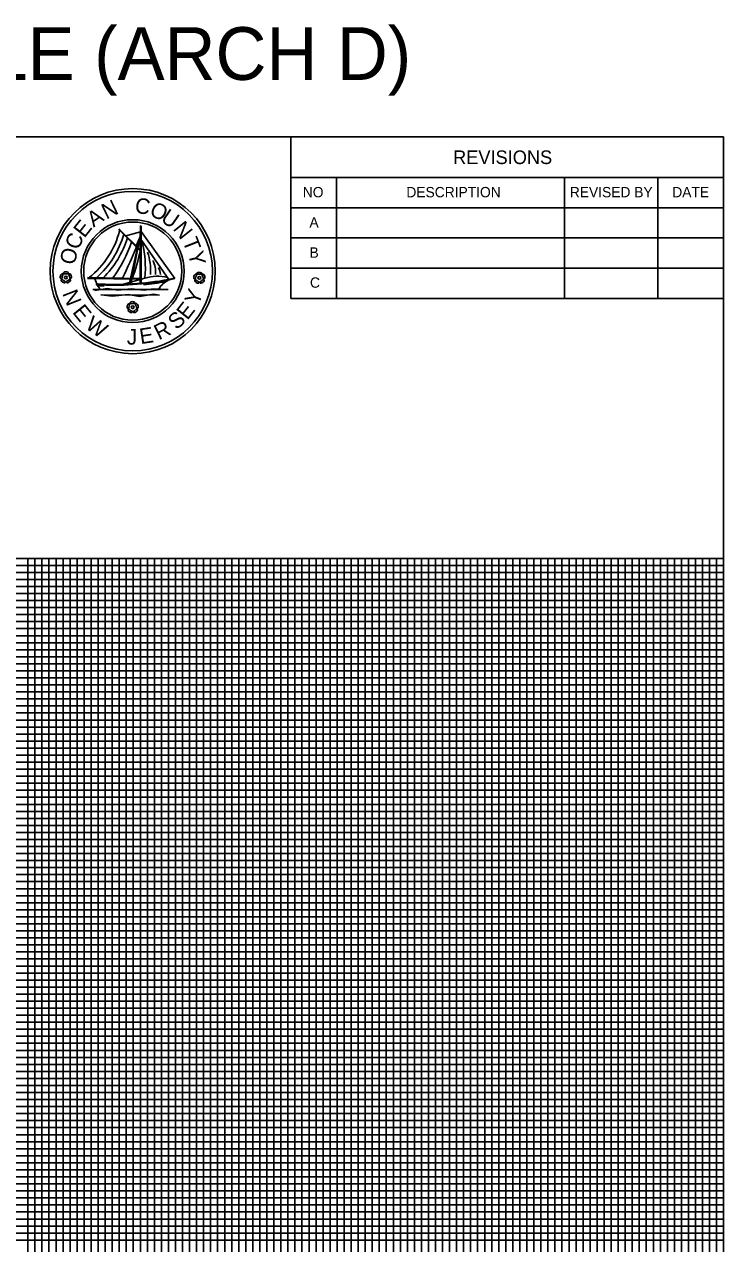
# Model space of a CAD drawing. Extents: x -6359 to 1641, y 3001 to 24737.
# Drawn here: x -2339 to 1641, y 17798 to 24737 of the extents above; entities that cross this region are included whole.
import ezdxf

# ---------------------------------------------------------------- set-up
doc = ezdxf.new("R2010")
doc.units = 0
for name, color, linetype in [('_grid', 7, 'Continuous'), ('Border', 7, 'Continuous'), ('Level 1', 7, 'Continuous'), ('TB - ON', 7, 'Continuous'), ('Title Block', 7, 'Continuous')]:
    doc.layers.add(name, color=color, linetype=linetype)

msp = doc.modelspace()

# ---------------------------------------------------------------- linework, layer by layer
at = {"layer": '_grid'}
for p, q in [((1641.3, 21698.2), (-6358.7, 21698.2)), ((1641.3, 21698.2), (-6358.7, 21698.2)), ((1641.3, 21658.2), (-6358.7, 21658.2)), ((-2318.7, 12898.2), (-2318.7, 21698.2)), ((-2278.7, 12898.2), (-2278.7, 21698.2)), ((-2238.7, 12898.2), (-2238.7, 21698.2)), ((-2198.7, 12898.2), (-2198.7, 21698.2)), ((-2158.7, 12898.2), (-2158.7, 21698.2)), ((-2118.7, 12898.2), (-2118.7, 21698.2)), ((-2078.7, 12898.2), (-2078.7, 21698.2)), ((-2038.7, 12898.2), (-2038.7, 21698.2)), ((-1998.7, 12898.2), (-1998.7, 21698.2)), ((-1958.7, 21698.2), (-1958.7, 12898.2)), ((-1958.7, 12898.2), (-1958.7, 21698.2)), ((-1918.7, 12898.2), (-1918.7, 21698.2)), ((-1878.7, 12898.2), (-1878.7, 21698.2)), ((-1838.7, 12898.2), (-1838.7, 21698.2)), ((-1798.7, 12898.2), (-1798.7, 21698.2)), ((-1758.7, 12898.2), (-1758.7, 21698.2)), ((-1718.7, 12898.2), (-1718.7, 21698.2)), ((-1678.7, 12898.2), (-1678.7, 21698.2)), ((-1638.7, 12898.2), (-1638.7, 21698.2)), ((-1598.7, 12898.2), (-1598.7, 21698.2)), ((-1558.7, 21698.2), (-1558.7, 12898.2)), ((-1558.7, 12898.2), (-1558.7, 21698.2)), ((-1518.7, 12898.2), (-1518.7, 21698.2)), ((-1478.7, 12898.2), (-1478.7, 21698.2)), ((-1438.7, 12898.2), (-1438.7, 21698.2)), ((-1398.7, 12898.2), (-1398.7, 21698.2)), ((-1358.7, 12898.2), (-1358.7, 21698.2)), ((-1318.7, 12898.2), (-1318.7, 21698.2)), ((-1278.7, 12898.2), (-1278.7, 21698.2)), ((-1238.7, 12898.2), (-1238.7, 21698.2)), ((-1198.7, 12898.2), (-1198.7, 21698.2)), ((-1158.7, 21698.2), (-1158.7, 12898.2)), ((-1158.7, 12898.2), (-1158.7, 21698.2)), ((-1118.7, 12898.2), (-1118.7, 21698.2)), ((-1078.7, 12898.2), (-1078.7, 21698.2)), ((-1038.7, 12898.2), (-1038.7, 21698.2)), ((-998.7, 12898.2), (-998.7, 21698.2)), ((-958.7, 12898.2), (-958.7, 21698.2)), ((-918.7, 12898.2), (-918.7, 21698.2)), ((-878.7, 12898.2), (-878.7, 21698.2)), ((-838.7, 12898.2), (-838.7, 21698.2)), ((-798.7, 12898.2), (-798.7, 21698.2)), ((-758.7, 21698.2), (-758.7, 12898.2)), ((-758.7, 12898.2), (-758.7, 21698.2)), ((-718.7, 12898.2), (-718.7, 21698.2)), ((-678.7, 12898.2), (-678.7, 21698.2)), ((-638.7, 12898.2), (-638.7, 21698.2)), ((-598.7, 12898.2), (-598.7, 21698.2)), ((-558.7, 12898.2), (-558.7, 21698.2)), ((-518.7, 12898.2), (-518.7, 21698.2)), ((-478.7, 12898.2), (-478.7, 21698.2)), ((-438.7, 12898.2), (-438.7, 21698.2)), ((-398.7, 12898.2), (-398.7, 21698.2)), ((-358.7, 21698.2), (-358.7, 12898.2)), ((-358.7, 12898.2), (-358.7, 21698.2)), ((-318.7, 12898.2), (-318.7, 21698.2)), ((-278.7, 12898.2), (-278.7, 21698.2)), ((-238.7, 12898.2), (-238.7, 21698.2)), ((-198.7, 12898.2), (-198.7, 21698.2)), ((-158.7, 12898.2), (-158.7, 21698.2)), ((-118.7, 12898.2), (-118.7, 21698.2)), ((-78.7, 12898.2), (-78.7, 21698.2)), ((-38.7, 12898.2), (-38.7, 21698.2)), ((1.3, 12898.2), (1.3, 21698.2)), ((41.3, 21698.2), (41.3, 12898.2)), ((41.3, 12898.2), (41.3, 21698.2)), ((81.3, 12898.2), (81.3, 21698.2)), ((121.3, 12898.2), (121.3, 21698.2)), ((161.3, 12898.2), (161.3, 21698.2)), ((201.3, 12898.2), (201.3, 21698.2)), ((241.3, 12898.2), (241.3, 21698.2)), ((281.3, 12898.2), (281.3, 21698.2)), ((321.3, 12898.2), (321.3, 21698.2)), ((361.3, 12898.2), (361.3, 21698.2)), ((401.3, 12898.2), (401.3, 21698.2)), ((441.3, 21698.2), (441.3, 12898.2)), ((441.3, 12898.2), (441.3, 21698.2)), ((481.3, 12898.2), (481.3, 21698.2)), ((521.3, 12898.2), (521.3, 21698.2)), ((561.3, 12898.2), (561.3, 21698.2)), ((601.3, 12898.2), (601.3, 21698.2)), ((641.3, 12898.2), (641.3, 21698.2)), ((681.3, 12898.2), (681.3, 21698.2)), ((721.3, 12898.2), (721.3, 21698.2)), ((761.3, 12898.2), (761.3, 21698.2)), ((801.3, 12898.2), (801.3, 21698.2)), ((841.3, 21698.2), (841.3, 12898.2)), ((841.3, 12898.2), (841.3, 21698.2)), ((881.3, 12898.2), (881.3, 21698.2)), ((921.3, 12898.2), (921.3, 21698.2)), ((961.3, 12898.2), (961.3, 21698.2)), ((1001.3, 12898.2), (1001.3, 21698.2)), ((1041.3, 12898.2), (1041.3, 21698.2)), ((1081.3, 12898.2), (1081.3, 21698.2)), ((1121.3, 12898.2), (1121.3, 21698.2)), ((1161.3, 12898.2), (1161.3, 21698.2)), ((1201.3, 12898.2), (1201.3, 21698.2)), ((1241.3, 21698.2), (1241.3, 12898.2)), ((1241.3, 12898.2), (1241.3, 21698.2)), ((1281.3, 12898.2), (1281.3, 21698.2)), ((1321.3, 12898.2), (1321.3, 21698.2)), ((1361.3, 12898.2), (1361.3, 21698.2)), ((1401.3, 12898.2), (1401.3, 21698.2)), ((1441.3, 12898.2), (1441.3, 21698.2)), ((1481.3, 12898.2), (1481.3, 21698.2)), ((1521.3, 12898.2), (1521.3, 21698.2)), ((1561.3, 12898.2), (1561.3, 21698.2)), ((1601.3, 12898.2), (1601.3, 21698.2)), ((1641.3, 12898.2), (1641.3, 21698.2)), ((1641.3, 21698.2), (1641.3, 12898.2)), ((1641.3, 21618.2), (-6358.7, 21618.2)), ((1641.3, 21578.2), (-6358.7, 21578.2)), ((1641.3, 21538.2), (-6358.7, 21538.2)), ((1641.3, 21498.2), (-6358.7, 21498.2)), ((1641.3, 21458.2), (-6358.7, 21458.2)), ((1641.3, 21418.2), (-6358.7, 21418.2)), ((1641.3, 21378.2), (-6358.7, 21378.2)), ((1641.3, 21338.2), (-6358.7, 21338.2)), ((1641.3, 21298.2), (-6358.7, 21298.2)), ((1641.3, 21298.2), (-6358.7, 21298.2)), ((1641.3, 21258.2), (-6358.7, 21258.2)), ((1641.3, 21218.2), (-6358.7, 21218.2)), ((1641.3, 21178.2), (-6358.7, 21178.2)), ((1641.3, 21138.2), (-6358.7, 21138.2)), ((1641.3, 21098.2), (-6358.7, 21098.2)), ((1641.3, 21058.2), (-6358.7, 21058.2)), ((1641.3, 21018.2), (-6358.7, 21018.2)), ((1641.3, 20978.2), (-6358.7, 20978.2)), ((1641.3, 20938.2), (-6358.7, 20938.2)), ((1641.3, 20898.2), (-6358.7, 20898.2)), ((1641.3, 20898.2), (-6358.7, 20898.2)), ((1641.3, 20858.2), (-6358.7, 20858.2)), ((1641.3, 20818.2), (-6358.7, 20818.2)), ((1641.3, 20778.2), (-6358.7, 20778.2)), ((1641.3, 20738.2), (-6358.7, 20738.2)), ((1641.3, 20698.2), (-6358.7, 20698.2)), ((1641.3, 20658.2), (-6358.7, 20658.2)), ((1641.3, 20618.2), (-6358.7, 20618.2)), ((1641.3, 20578.2), (-6358.7, 20578.2)), ((1641.3, 20538.2), (-6358.7, 20538.2)), ((1641.3, 20498.2), (-6358.7, 20498.2)), ((1641.3, 20498.2), (-6358.7, 20498.2)), ((1641.3, 20458.2), (-6358.7, 20458.2)), ((1641.3, 20418.2), (-6358.7, 20418.2)), ((1641.3, 20378.2), (-6358.7, 20378.2)), ((1641.3, 20338.2), (-6358.7, 20338.2)), ((1641.3, 20298.2), (-6358.7, 20298.2)), ((1641.3, 20258.2), (-6358.7, 20258.2)), ((1641.3, 20218.2), (-6358.7, 20218.2)), ((1641.3, 20178.2), (-6358.7, 20178.2)), ((1641.3, 20138.2), (-6358.7, 20138.2)), ((1641.3, 20098.2), (-6358.7, 20098.2)), ((1641.3, 20098.2), (-6358.7, 20098.2)), ((1641.3, 20058.2), (-6358.7, 20058.2)), ((1641.3, 20018.2), (-6358.7, 20018.2)), ((1641.3, 19978.2), (-6358.7, 19978.2)), ((1641.3, 19938.2), (-6358.7, 19938.2)), ((1641.3, 19898.2), (-6358.7, 19898.2)), ((1641.3, 19858.2), (-6358.7, 19858.2)), ((1641.3, 19818.2), (-6358.7, 19818.2)), ((1641.3, 19778.2), (-6358.7, 19778.2)), ((1641.3, 19738.2), (-6358.7, 19738.2)), ((1641.3, 19698.2), (-6358.7, 19698.2)), ((1641.3, 19698.2), (-6358.7, 19698.2)), ((1641.3, 19658.2), (-6358.7, 19658.2)), ((1641.3, 19618.2), (-6358.7, 19618.2)), ((1641.3, 19578.2), (-6358.7, 19578.2)), ((1641.3, 19538.2), (-6358.7, 19538.2)), ((1641.3, 19498.2), (-6358.7, 19498.2)), ((1641.3, 19458.2), (-6358.7, 19458.2)), ((1641.3, 19418.2), (-6358.7, 19418.2)), ((1641.3, 19378.2), (-6358.7, 19378.2)), ((1641.3, 19338.2), (-6358.7, 19338.2)), ((1641.3, 19298.2), (-6358.7, 19298.2)), ((1641.3, 19298.2), (-6358.7, 19298.2)), ((1641.3, 19258.2), (-6358.7, 19258.2)), ((1641.3, 19218.2), (-6358.7, 19218.2)), ((1641.3, 19178.2), (-6358.7, 19178.2)), ((1641.3, 19138.2), (-6358.7, 19138.2)), ((1641.3, 19098.2), (-6358.7, 19098.2)), ((1641.3, 19058.2), (-6358.7, 19058.2)), ((1641.3, 19018.2), (-6358.7, 19018.2)), ((1641.3, 18978.2), (-6358.7, 18978.2)), ((1641.3, 18938.2), (-6358.7, 18938.2)), ((1641.3, 18898.2), (-6358.7, 18898.2)), ((1641.3, 18898.2), (-6358.7, 18898.2)), ((1641.3, 18858.2), (-6358.7, 18858.2)), ((1641.3, 18818.2), (-6358.7, 18818.2)), ((1641.3, 18778.2), (-6358.7, 18778.2)), ((1641.3, 18738.2), (-6358.7, 18738.2)), ((1641.3, 18698.2), (-6358.7, 18698.2)), ((1641.3, 18658.2), (-6358.7, 18658.2)), ((1641.3, 18618.2), (-6358.7, 18618.2)), ((1641.3, 18578.2), (-6358.7, 18578.2)), ((1641.3, 18538.2), (-6358.7, 18538.2)), ((1641.3, 18498.2), (-6358.7, 18498.2)), ((1641.3, 18498.2), (-6358.7, 18498.2)), ((1641.3, 18458.2), (-6358.7, 18458.2)), ((1641.3, 18418.2), (-6358.7, 18418.2)), ((1641.3, 18378.2), (-6358.7, 18378.2)), ((1641.3, 18338.2), (-6358.7, 18338.2)), ((1641.3, 18298.2), (-6358.7, 18298.2)), ((1641.3, 18258.2), (-6358.7, 18258.2)), ((1641.3, 18218.2), (-6358.7, 18218.2)), ((1641.3, 18178.2), (-6358.7, 18178.2)), ((1641.3, 18138.2), (-6358.7, 18138.2)), ((1641.3, 18098.2), (-6358.7, 18098.2)), ((1641.3, 18098.2), (-6358.7, 18098.2)), ((1641.3, 18058.2), (-6358.7, 18058.2)), ((1641.3, 18018.2), (-6358.7, 18018.2)), ((1641.3, 17978.2), (-6358.7, 17978.2)), ((1641.3, 17938.2), (-6358.7, 17938.2)), ((1641.3, 17898.2), (-6358.7, 17898.2)), ((1641.3, 17858.2), (-6358.7, 17858.2)), ((1641.3, 17818.2), (-6358.7, 17818.2))]:
    msp.add_line(p, q, dxfattribs=at)
at = {"layer": 'Border'}
for p, q in [((-6358.7, 24098.2), (1641.3, 24098.2)), ((1641.3, 24098.2), (1641.3, 21698.2)), ((1641.3, 21698.2), (1641.3, 12898.2))]:
    msp.add_line(p, q, dxfattribs=at)
at = {"layer": 'TB - ON'}
for p, q in [((1641.3, 24098.2), (-6358.7, 24098.2)), ((-6358.7, 24098.2), (1641.3, 24098.2)), ((-822.7, 23177.8), (-822.7, 24098.2)), ((1641.3, 21698.2), (1641.3, 24098.2)), ((1641.3, 23865.6), (-822.7, 23865.6)), ((-562.1, 23177.8), (-562.1, 23865.6)), ((735.5, 23177.8), (735.5, 23865.6)), ((1267.3, 23177.8), (1267.3, 23865.6)), ((1641.3, 23693.7), (-822.7, 23693.7)), ((-1799.6, 23567.8), (-1679.5, 23449.3)), ((-1796.8, 23570.5), (-1679.9, 23455.1)), ((-1678.7, 23556.3), (-1760.5, 23534.6)), ((-1676, 23550.9), (-1742.3, 23259.6)), ((-1676, 23550.9), (-1731.9, 23260.1)), ((-1701.8, 23477.4), (-1678.8, 23527.3)), ((-1679.5, 23510.8), (-1678.2, 23588.6)), ((-1674.2, 23558.8), (-1482.2, 23290.5)), ((-1673.1, 23510.8), (-1674, 23589.4)), ((-1679.5, 23263.8), (-1679.5, 23510.8)), ((-1673.1, 23264.4), (-1673.1, 23510.8)), ((-1672.2, 23509.4), (-1516.5, 23285.7)), ((1641.3, 23521.7), (-822.7, 23521.7)), ((1641.3, 23349.8), (-822.7, 23349.8)), ((-1679.9, 23287), (-1979.3, 23291.6)), ((-1679.8, 23291.4), (-1979.2, 23296)), ((-1937.3, 23289.4), (-1925.9, 23259.9)), ((-1652.7, 23292), (-1773.8, 23258.3)), ((-1520, 23280.6), (-1482.2, 23290.5)), ((-1519.6, 23285.1), (-1481.6, 23292.1)), ((-1948.5, 23227.8), (-1520.8, 23227.8)), ((-1867.3, 23233.6), (-1938.4, 23223.6)), ((-1903.6, 23197.1), (-1569, 23195.5)), ((-1840, 23190.9), (-1900.3, 23197.3)), ((-1806.9, 23224.2), (-1867.3, 23233.6)), ((-1745.7, 23200.5), (-1840, 23190.9)), ((-1730.8, 23232.8), (-1806.9, 23224.2)), ((-1683.5, 23189.5), (-1745.7, 23200.5)), ((-1657, 23224), (-1730.8, 23232.8)), ((-1604.2, 23201.6), (-1683.5, 23189.5)), ((-1604.3, 23233.1), (-1657, 23224)), ((-1520.8, 23227.8), (-1604.3, 23233.1)), ((-1569, 23195.5), (-1604.2, 23201.6)), ((1641.3, 23177.8), (-822.7, 23177.8))]:
    msp.add_line(p, q, dxfattribs=at)
for centre, radius in [((-1721.9, 23333), 469.8), ((-1721.9, 23333), 454), ((-1721.9, 23333), 292.8), ((-1721.9, 23333), 279.3), ((-2102.6, 23296.7), 7.87), ((-1342.7, 23294.5), 7.87), ((-1722.4, 23127.1), 7.87)]:
    msp.add_circle(centre, radius, dxfattribs=at)
for centre, radius, start, end in [((-2271, 23681.3), 488.5, 307.90444, 346.21233), ((-2271, 23681.3), 516.5, 311.62946, 344.37175), ((-1798.3, 23569.3), 1.94, 39.72611, 230.2739), ((-1676.1, 23588.7), 2.15, 19.75004, 182.7703), ((-2271, 23681.3), 542.4, 314.52857, 342.86997), ((-2409.8, 23723.9), 717.1, 323.15333, 341.66107), ((-5038.8, 24847), 3610.5, 334.50551, 337.58996), ((-2226.3, 23350), 576.5, 354.22434, 16.04693), ((-2860.5, 23697.2), 1206.8, 340.38579, 348.14661), ((-1942.2, 23337.8), 321.5, 355.78399, 18.8142), ((-1736.4, 23326.8), 144.9, 355.16039, 27.78371), ((-2108, 23298.3), 26.5, 137.15758, 188.57474), ((-2124.3, 23313.4), 4.19, 83.65018, 137.15758), ((-2124.5, 23311.6), 6, 49.01818, 83.65018), ((-2123.3, 23313), 4.19, 325.35921, 49.01818), ((-2112.7, 23322.2), 4.19, 116.57474, 177.34614), ((-2111.1, 23322.2), 5.8, 177.34614, 223.93293), ((-2112.3, 23321), 4.19, 223.93293, 289.1485), ((-2102.8, 23302.3), 26.5, 65.15758, 116.57474), ((-2102.3, 23292.2), 26.3, 73.35921, 109.1485), ((-2093.5, 23321.4), 4.19, 253.35921, 337.01818), ((-2093.4, 23322.5), 4.19, 11.65018, 65.15758), ((-2095.2, 23322.2), 6, 337.01818, 11.65018), ((-2082.5, 23313.4), 4.19, 151.93293, 217.1485), ((-2081.1, 23312.7), 5.8, 105.34614, 151.93293), ((-2081.5, 23314.2), 4.19, 44.57474, 105.34614), ((-2097.3, 23298.6), 26.5, 353.15758, 44.57474), ((-1653.7, 23310.1), 89.6, 2.62489, 29.2339), ((-1364.4, 23311.3), 4.19, 83.65018, 137.15758), ((-1364.6, 23309.5), 6, 49.01818, 83.65018), ((-1352.8, 23320), 4.19, 116.57474, 177.34614), ((-1351.2, 23320), 5.8, 177.34614, 223.93293), ((-1352.4, 23318.9), 4.19, 223.93293, 289.1485), ((-1342.9, 23300.1), 26.5, 65.15758, 116.57474), ((-1342.4, 23290), 26.3, 73.35921, 109.1485), ((-1333.6, 23319.3), 4.19, 253.35921, 337.01818), ((-1333.5, 23320.3), 4.19, 11.65018, 65.15758), ((-1335.3, 23320), 6, 337.01818, 11.65018), ((-1321.2, 23310.5), 5.8, 105.34614, 151.93293), ((-1321.6, 23312), 4.19, 44.57474, 105.34614), ((-2130, 23295), 4.19, 188.57474, 249.34614), ((-2129.4, 23296.5), 5.8, 249.34614, 295.93293), ((-2125.2, 23281.2), 4.19, 155.65018, 209.15758), ((-2123.6, 23280.5), 6, 121.01818, 155.65018), ((-2105.8, 23292.1), 26.5, 209.15758, 260.57474), ((-2128.7, 23295), 4.19, 295.93293, 1.1485), ((-2124.5, 23282.1), 4.19, 37.35921, 121.01818), ((-2098.2, 23295.7), 26.3, 145.35921, 181.1485), ((-2100.3, 23300.6), 26.3, 217.35921, 253.1485), ((-2109.4, 23270.1), 4.19, 260.57474, 321.34614), ((-2109.1, 23271.4), 4.19, 7.93293, 73.1485), ((-2110.7, 23271.1), 5.8, 321.34614, 7.93293), ((-2095.4, 23271.4), 4.19, 109.35921, 193.01818), ((-2093.7, 23271.8), 6, 193.01818, 227.65018), ((-2094.9, 23270.4), 4.19, 227.65018, 281.15758), ((-2105.6, 23300.2), 26.3, 289.35921, 325.1485), ((-2099.2, 23292.3), 26.5, 281.15758, 332.57474), ((-2106.8, 23295), 26.3, 1.35921, 37.1485), ((-2080.5, 23282.7), 4.19, 79.93293, 145.1485), ((-2076.3, 23295.7), 4.19, 181.35921, 265.01818), ((-2080.8, 23281.1), 5.8, 33.34614, 79.93293), ((-2076.1, 23297.5), 6, 265.01818, 299.65018), ((-2079.5, 23282), 4.19, 332.57474, 33.34614), ((-2075.2, 23295.9), 4.19, 299.65018, 353.15758), ((-1829.9, 25004.1), 1746.8, 266.69795, 280.23111), ((-2005.7, 23182.8), 107.9, 25.67969, 45.85063), ((-1829.9, 25004.1), 1751.2, 266.85432, 280.194), ((-1829.9, 25004.1), 1756.4, 267.01816, 268.24015), ((-1829.9, 25004.1), 1756.4, 275.55716, 279.66812), ((-1580.7, 23083.5), 220.6, 75.17554, 109.03876), ((-1476.5, 23181.1), 108.6, 113.60998, 152.69479), ((-1348.1, 23296.1), 26.5, 137.15758, 188.57474), ((-1370.1, 23292.8), 4.19, 188.57474, 249.34614), ((-1369.5, 23294.3), 5.8, 249.34614, 295.93293), ((-1365.3, 23279.1), 4.19, 155.65018, 209.15758), ((-1363.7, 23278.3), 6, 121.01818, 155.65018), ((-1345.9, 23289.9), 26.5, 209.15758, 260.57474), ((-1368.8, 23292.9), 4.19, 295.93293, 1.1485), ((-1364.6, 23279.9), 4.19, 37.35921, 121.01818), ((-1338.3, 23293.5), 26.3, 145.35921, 181.1485), ((-1340.4, 23298.4), 26.3, 217.35921, 253.1485), ((-1363.4, 23310.8), 4.19, 325.35921, 49.01818), ((-1349.5, 23268), 4.19, 260.57474, 321.34614), ((-1349.2, 23269.2), 4.19, 7.93293, 73.1485), ((-1350.8, 23269), 5.8, 321.34614, 7.93293), ((-1335.5, 23269.2), 4.19, 109.35921, 193.01818), ((-1333.8, 23269.6), 6, 193.01818, 227.65018), ((-1335, 23268.2), 4.19, 227.65018, 281.15758), ((-1345.7, 23298), 26.3, 289.35921, 325.1485), ((-1339.3, 23290.1), 26.5, 281.15758, 332.57474), ((-1322.6, 23311.2), 4.19, 151.93293, 217.1485), ((-1346.9, 23292.8), 26.3, 1.35921, 37.1485), ((-1320.6, 23280.5), 4.19, 79.93293, 145.1485), ((-1316.4, 23293.5), 4.19, 181.35921, 265.01818), ((-1320.9, 23278.9), 5.8, 33.34614, 79.93293), ((-1337.4, 23296.4), 26.5, 353.15758, 44.57474), ((-1316.2, 23295.3), 6, 265.01818, 299.65018), ((-1319.6, 23279.8), 4.19, 332.57474, 33.34614), ((-1315.3, 23293.8), 4.19, 299.65018, 353.15758), ((-1727.8, 23128.7), 26.5, 137.15758, 188.57474), ((-1749.8, 23125.4), 4.19, 188.57474, 249.34614), ((-1749.2, 23126.9), 5.8, 249.34614, 295.93293), ((-1745, 23111.6), 4.19, 155.65018, 209.15758), ((-1743.4, 23110.9), 6, 121.01818, 155.65018), ((-1725.6, 23122.5), 26.5, 209.15758, 260.57474), ((-1744.1, 23143.8), 4.19, 83.65018, 137.15758), ((-1748.5, 23125.4), 4.19, 295.93293, 1.1485), ((-1744.3, 23112.4), 4.19, 37.35921, 121.01818), ((-1718, 23126), 26.3, 145.35921, 181.1485), ((-1744.3, 23142), 6, 49.01818, 83.65018), ((-1720, 23130.9), 26.3, 217.35921, 253.1485), ((-1743.1, 23143.4), 4.19, 325.35921, 49.01818), ((-1732.5, 23152.6), 4.19, 116.57474, 177.34614), ((-1730.9, 23152.5), 5.8, 177.34614, 223.93293), ((-1732.1, 23151.4), 4.19, 223.93293, 289.1485), ((-1722.5, 23132.7), 26.5, 65.15758, 116.57474), ((-1722, 23122.6), 26.3, 73.35921, 109.1485), ((-1725.3, 23130.5), 26.3, 289.35921, 325.1485), ((-1713.3, 23151.8), 4.19, 253.35921, 337.01818), ((-1719, 23122.6), 26.5, 281.15758, 332.57474), ((-1713.2, 23152.9), 4.19, 11.65018, 65.15758), ((-1715, 23152.5), 6, 337.01818, 11.65018), ((-1702.3, 23143.8), 4.19, 151.93293, 217.1485), ((-1700.8, 23143), 5.8, 105.34614, 151.93293), ((-1726.6, 23125.3), 26.3, 1.35921, 37.1485), ((-1700.3, 23113.1), 4.19, 79.93293, 145.1485), ((-1701.3, 23144.6), 4.19, 44.57474, 105.34614), ((-1696.1, 23126.1), 4.19, 181.35921, 265.01818), ((-1700.6, 23111.5), 5.8, 33.34614, 79.93293), ((-1717.1, 23129), 26.5, 353.15758, 44.57474), ((-1695.9, 23127.9), 6, 265.01818, 299.65018), ((-1699.2, 23112.4), 4.19, 332.57474, 33.34614), ((-1695, 23126.3), 4.19, 299.65018, 353.15758), ((-1729.2, 23100.5), 4.19, 260.57474, 321.34614), ((-1728.9, 23101.7), 4.19, 7.93293, 73.1485), ((-1730.5, 23101.5), 5.8, 321.34614, 7.93293), ((-1715.2, 23101.7), 4.19, 109.35921, 193.01818), ((-1713.5, 23102.1), 6, 193.01818, 227.65018), ((-1714.7, 23100.8), 4.19, 227.65018, 281.15758)]:
    msp.add_arc(centre, radius, start, end, dxfattribs=at)
at = {"layer": 'Title Block'}
msp.add_line((1641.3, 24098.2), (1641.3, 10898.2), dxfattribs=at)

# ---------------------------------------------------------------- texts
at = {"layer": 'Level 1'}
msp.add_text('PLOT AT 400 SCALE (ARCH D)', height=300, dxfattribs=at).set_placement((-5932.9, 24421.3))
at = {"layer": 'TB - ON'}
for s, height, rotation, p in [('REVISIONS', 77.44, 0.01594, (101.5, 23942.2)), ('NO', 58.75, 0.01594, (-754.1, 23753.1)), ('DESCRIPTION', 58.752, 0.01594, (-164.5, 23753.1)), ('REVISED BY', 58.75, 0.01594, (765.9, 23753.1)), ('DATE', 58.75, 0.01594, (1349, 23753.1)), ('N', 88.5, 25.80621, (-1872.6, 23626.3)), ('C', 88.5, 351.49326, (-1713.9, 23665.6)), ('A', 88.5, 34.38445, (-1944.9, 23580.1)), ('O', 88.5, 334.33678, (-1632.6, 23653.7)), ('U', 88.5, 325.75854, (-1568.1, 23619.8)), ('E', 88.5, 51.54092, (-1997.6, 23517.5)), ('N', 88.5, 308.60207, (-1496.9, 23572.4)), ('A', 58.8, 0.01594, (-716.2, 23581.2)), ('C', 88.5, 68.6974, (-2029.3, 23449.4)), ('T', 88.5, 291.44559, (-1440.1, 23504.3)), ('O', 88.5, 77.27564, (-2052.8, 23364.4)), ('B', 58.8, 0.01594, (-715.8, 23409.3)), ('Y', 88.5, 282.86736, (-1408.2, 23436.2)), ('C', 58.8, 0.01594, (-713, 23238.5)), ('N', 88.5, 291.58859, (-2124.3, 23206.1)), ('Y', 88.5, 68.84039, (-1348.4, 23135.1)), ('E', 88.5, 308.74506, (-2068.9, 23098.3)), ('E', 88.5, 51.68392, (-1411.1, 23050.2)), ('W', 88.5, 325.90154, (-1997.5, 23010.5)), ('R', 88.5, 25.9492, (-1573.4, 22938.8)), ('S', 88.5, 43.10568, (-1471.4, 22995.3)), ('J', 88.5, 0.21449, (-1755.7, 22914.5)), ('E', 88.5, 8.79273, (-1676.7, 22917))]:
    msp.add_text(s, height=height, rotation=rotation, dxfattribs=at).set_placement(p)

doc.saveas('drawing.dxf')
